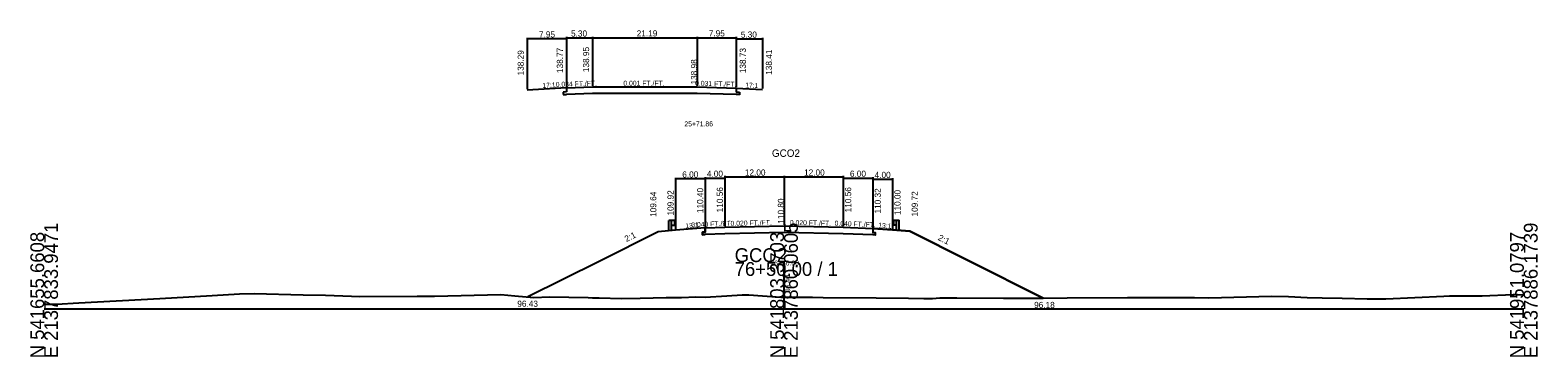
# Model space of a CAD drawing. Extents: x -14327 to 8886, y -10 to 39048.
# Drawn here: x 2997.2 to 3302.8, y 12990.3 to 13056.4 of the extents above; entities that cross this region are included whole.
import ezdxf

# ---------------------------------------------------------------- set-up
doc = ezdxf.new("R2010")
doc.units = 0
for name, color, linetype in [('Level 1', 7, 'Continuous'), ('Level 20', 7, 'Continuous'), ('Level 5', 7, 'Continuous'), ('Level 53', 7, 'Continuous'), ('Level 54', 7, 'Continuous'), ('Level 55', 7, 'Continuous'), ('Level 7', 7, 'Continuous'), ('RD_GPK_XS_Cell', 7, 'Continuous'), ('RD_XS_EwShp', 7, 'Continuous'), ('RD_XS_ExGround', 7, 'Continuous'), ('RD_XS_Pave', 7, 'Continuous'), ('RD_XS_TX_Baseline', 7, 'Continuous'), ('RD_XS_TX_Elev_EX', 7, 'Continuous'), ('RD_XS_TX_Elev_PR', 7, 'Continuous'), ('RD_XS_TX_Station', 7, 'Continuous')]:
    doc.layers.add(name, color=color, linetype=linetype)

msp = doc.modelspace()

# ---------------------------------------------------------------- linework, layer by layer
at = {"layer": 'Level 1'}
for p, q in [((3126.66, 13015.92), (3126.66, 13017.9)), ((3127.22, 13017.9), (3126.66, 13017.9)), ((3127.22, 13015.92), (3127.22, 13017.9)), ((3127.77, 13017.9), (3127.22, 13017.9)), ((3127.77, 13016.93), (3127.22, 13016.93)), ((3127.77, 13017.9), (3127.77, 13016.93)), ((3127.85, 13017.83), (3127.77, 13017.84)), ((3127.85, 13017), (3127.77, 13016.99)), ((3127.84, 13017.49), (3127.84, 13017.34)), ((3127.98, 13017.73), (3127.86, 13017.82)), ((3127.98, 13017.63), (3127.86, 13017.54)), ((3127.98, 13017.2), (3127.86, 13017.29)), ((3127.98, 13017.1), (3127.86, 13017.01)), ((3172.02, 13017.81), (3172.14, 13017.9)), ((3172.02, 13017.71), (3172.14, 13017.62)), ((3172.02, 13017.28), (3172.14, 13017.37)), ((3172.02, 13017.18), (3172.14, 13017.09)), ((3172.15, 13017.91), (3172.23, 13017.92)), ((3172.15, 13017.08), (3172.23, 13017.07)), ((3172.16, 13017.57), (3172.16, 13017.42)), ((3172.23, 13017.98), (3172.23, 13017.01)), ((3172.23, 13017.98), (3172.78, 13017.98)), ((3172.23, 13017.01), (3172.78, 13017.01)), ((3172.78, 13016), (3172.78, 13017.98)), ((3172.78, 13017.98), (3173.34, 13017.98)), ((3173.34, 13016), (3173.34, 13017.98))]:
    msp.add_line(p, q, dxfattribs=at)
for centre, radius, start, end in [((3127.91, 13017.49), 0.0651, 135, 180), ((3127.91, 13017.34), 0.0651, 180, 237.0105), ((3127.85, 13017.8), 0.026, 50.9495, 90), ((3127.85, 13017.03), 0.026, 270, 309.0504), ((3127.93, 13017.68), 0.0651, 309.0337, 50.9664), ((3127.93, 13017.15), 0.0651, 309.0337, 50.9664), ((3172.07, 13017.76), 0.0651, 129.0336, 230.9663), ((3172.07, 13017.23), 0.0651, 129.0336, 230.9663), ((3172.09, 13017.42), 0.0651, 302.9895, 0), ((3172.15, 13017.88), 0.026, 90, 129.0505), ((3172.09, 13017.57), 0.0651, 0, 45), ((3172.15, 13017.11), 0.026, 230.9496, 270)]:
    msp.add_arc(centre, radius, start, end, dxfattribs=at)
at = {"layer": 'Level 20'}
for p, q in [((3097.94, 13054.92), (3097.94, 13044.49)), ((3105.89, 13054.72), (3097.94, 13054.72)), ((3105.89, 13055.1), (3105.89, 13044.97)), ((3105.89, 13054.92), (3105.89, 13044.97)), ((3105.89, 13054.9), (3111.19, 13054.9)), ((3111.19, 13055.13), (3111.19, 13045.15)), ((3111.19, 13055.1), (3111.19, 13045.15)), ((3111.19, 13054.93), (3132.38, 13054.93)), ((3132.38, 13055.13), (3132.38, 13045.18)), ((3132.38, 13054.93), (3140.32, 13054.93)), ((3140.32, 13055.13), (3140.32, 13044.93)), ((3140.32, 13054.88), (3140.32, 13044.93)), ((3140.32, 13054.68), (3145.62, 13054.68)), ((3145.62, 13054.88), (3145.62, 13044.61)), ((3105.89, 13044.77), (3097.94, 13044.29)), ((3105.89, 13043.94), (3105.23, 13043.92)), ((3105.23, 13043.92), (3105.23, 13043.42)), ((3105.23, 13043.42), (3105.89, 13043.44)), ((3105.89, 13044.77), (3111.19, 13044.95)), ((3105.89, 13044.77), (3105.89, 13043.94)), ((3111.19, 13043.62), (3105.89, 13043.44)), ((3111.19, 13044.95), (3132.38, 13044.98)), ((3132.38, 13043.65), (3111.19, 13043.62)), ((3132.38, 13044.98), (3140.32, 13044.73)), ((3140.32, 13043.4), (3132.38, 13043.65)), ((3140.32, 13044.73), (3140.32, 13043.9)), ((3140.32, 13044.73), (3145.62, 13044.41)), ((3140.32, 13043.9), (3140.99, 13043.88)), ((3140.99, 13043.88), (3140.99, 13043.38)), ((3140.99, 13043.38), (3140.32, 13043.4))]:
    msp.add_line(p, q, dxfattribs=at)
at = {"layer": 'Level 5'}
for p, q in [((3134, 13016.4), (3134, 13015.56)), ((3168, 13016.32), (3168, 13015.48)), ((3134, 13015.56), (3133.5, 13015.54)), ((3133.5, 13015.54), (3133.5, 13015.04)), ((3133.5, 13015.04), (3134, 13015.06)), ((3138, 13015.22), (3134, 13015.06)), ((3150, 13015.46), (3138, 13015.22)), ((3162, 13015.22), (3150, 13015.46)), ((3168, 13014.98), (3162, 13015.22)), ((3168, 13015.48), (3168.5, 13015.46)), ((3168.5, 13014.96), (3168, 13014.98)), ((3168.5, 13015.46), (3168.5, 13014.96))]:
    msp.add_line(p, q, dxfattribs=at)
at = {"layer": 'Level 54'}
for p, q in [((3128, 13026.55), (3128, 13016.12)), ((3134, 13026.35), (3128, 13026.35)), ((3134, 13026.71), (3134, 13016.6)), ((3134, 13026.55), (3134, 13016.6)), ((3134, 13026.51), (3138, 13026.51)), ((3138, 13026.95), (3138, 13016.76)), ((3138, 13026.75), (3150, 13026.75)), ((3138, 13026.71), (3138, 13016.76)), ((3150, 13026.95), (3150, 13017)), ((3150, 13026.75), (3162, 13026.75)), ((3162, 13026.95), (3162, 13016.76)), ((3162, 13026.71), (3162, 13016.76)), ((3162, 13026.51), (3168, 13026.51)), ((3168, 13026.71), (3168, 13016.52)), ((3168, 13026.47), (3168, 13016.52)), ((3168, 13026.27), (3172, 13026.27)), ((3172, 13026.47), (3172, 13016.2))]:
    msp.add_line(p, q, dxfattribs=at)
at = {"layer": 'Level 7'}
for p, q in [((3134, 13016.4), (3128, 13015.92)), ((3168, 13016.32), (3172, 13016)), ((3172, 13016), (3175.5, 13015.72)), ((3124.5, 13015.64), (3112.5, 13009.64)), ((3128, 13015.92), (3124.5, 13015.64)), ((3175.5, 13015.72), (3187.5, 13009.72)), ((3112.5, 13009.64), (3098.09, 13002.43)), ((3187.5, 13009.72), (3202.57, 13002.18))]:
    msp.add_line(p, q, dxfattribs=at)
at = {"layer": 'RD_GPK_XS_Cell'}
for p, q in [((3150, 13000), (3150, 13009.49)), ((3000, 13000), (3150, 13000)), ((3150, 13000), (3300, 13000))]:
    msp.add_line(p, q, dxfattribs=at)
at = {"layer": 'RD_XS_EwShp'}
msp.add_lwpolyline([(3194.52, 13002.16), (3198.96, 13002.15), (3202.57, 13002.18), (3187.5, 13009.72), (3175.5, 13015.72), (3172, 13016), (3168, 13016.32), (3168, 13015.48), (3168.5, 13015.46), (3168.5, 13014.96), (3168, 13014.98), (3162, 13015.22), (3150, 13015.46), (3138, 13015.22), (3134, 13015.06), (3133.5, 13015.04), (3133.5, 13015.54), (3134, 13015.56), (3134, 13016.4), (3128, 13015.92), (3124.5, 13015.64), (3112.5, 13009.64), (3098.09, 13002.43), (3099.29, 13002.32), (3102.48, 13002.42), (3110.32, 13002.32), (3111.19, 13002.27), (3112.5, 13002.27), (3117.05, 13002.14), (3120.82, 13002.21), (3126.14, 13002.29), (3129.21, 13002.31), (3132.15, 13002.44), (3134.03, 13002.39), (3138.41, 13002.66), (3141.5, 13002.85), (3142.88, 13002.85), (3149.35, 13002.41), (3150, 13002.4), (3155.79, 13002.36), (3157.97, 13002.33), (3168.7, 13002.25), (3175.26, 13002.16), (3178.34, 13002.09), (3180.08, 13002.14), (3181.61, 13002.25), (3185.02, 13002.26)], close=True, dxfattribs=at)
at = {"layer": 'RD_XS_ExGround'}
for p, q in [((3000, 13000.99), (3001.17, 13000.94)), ((3001.17, 13000.94), (3002.49, 13000.99)), ((3002.49, 13000.99), (3007.01, 13001.25)), ((3007.01, 13001.25), (3023.45, 13002.13)), ((3023.45, 13002.13), (3034.08, 13002.72)), ((3034.08, 13002.72), (3039.58, 13003.05)), ((3039.58, 13003.05), (3042.6, 13003.16)), ((3042.6, 13003.16), (3052.5, 13002.87)), ((3052.5, 13002.87), (3057.07, 13002.82)), ((3057.07, 13002.82), (3062.31, 13002.59)), ((3062.31, 13002.59), (3063.97, 13002.49)), ((3063.97, 13002.49), (3075.61, 13002.59)), ((3075.61, 13002.59), (3078.32, 13002.61)), ((3078.32, 13002.61), (3079.12, 13002.61)), ((3079.12, 13002.61), (3092.62, 13002.9)), ((3092.62, 13002.9), (3095.45, 13002.68)), ((3095.45, 13002.68), (3099.29, 13002.32)), ((3099.29, 13002.32), (3102.48, 13002.42)), ((3102.48, 13002.42), (3110.32, 13002.32)), ((3110.32, 13002.32), (3111.19, 13002.27)), ((3111.19, 13002.27), (3112.5, 13002.27)), ((3112.5, 13002.27), (3117.05, 13002.14)), ((3117.05, 13002.14), (3120.82, 13002.21)), ((3120.82, 13002.21), (3126.14, 13002.29)), ((3126.14, 13002.29), (3129.21, 13002.31)), ((3129.21, 13002.31), (3132.15, 13002.44)), ((3132.15, 13002.44), (3134.03, 13002.39)), ((3134.03, 13002.39), (3138.41, 13002.66)), ((3138.41, 13002.66), (3141.5, 13002.85)), ((3141.5, 13002.85), (3142.88, 13002.85)), ((3142.88, 13002.85), (3149.35, 13002.41)), ((3149.35, 13002.41), (3150, 13002.4)), ((3150, 13002.4), (3155.79, 13002.36)), ((3155.79, 13002.36), (3157.97, 13002.33)), ((3157.97, 13002.33), (3168.7, 13002.25)), ((3168.7, 13002.25), (3175.26, 13002.16)), ((3175.26, 13002.16), (3178.34, 13002.09)), ((3178.34, 13002.09), (3180.08, 13002.14)), ((3180.08, 13002.14), (3181.61, 13002.25)), ((3181.61, 13002.25), (3185.02, 13002.26)), ((3185.02, 13002.26), (3194.52, 13002.16)), ((3194.52, 13002.16), (3198.96, 13002.15)), ((3198.96, 13002.15), (3207.43, 13002.23)), ((3207.43, 13002.23), (3219.62, 13002.33)), ((3219.62, 13002.33), (3220.84, 13002.34)), ((3220.84, 13002.34), (3221.41, 13002.35)), ((3221.41, 13002.35), (3233.26, 13002.29)), ((3233.26, 13002.29), (3236.16, 13002.26)), ((3236.16, 13002.26), (3248.86, 13002.59)), ((3248.86, 13002.59), (3252.26, 13002.51)), ((3252.26, 13002.51), (3256.05, 13002.34)), ((3256.05, 13002.34), (3259.08, 13002.26)), ((3259.08, 13002.26), (3263.14, 13002.15)), ((3263.14, 13002.15), (3268.21, 13002.02)), ((3268.21, 13002.02), (3271.99, 13002.04)), ((3271.99, 13002.04), (3283.81, 13002.58)), ((3283.81, 13002.58), (3284.9, 13002.64)), ((3284.9, 13002.64), (3291.55, 13002.63)), ((3291.55, 13002.63), (3297.81, 13002.91)), ((3297.81, 13002.91), (3298.73, 13002.94)), ((3298.73, 13002.94), (3300, 13002.88))]:
    msp.add_line(p, q, dxfattribs=at)
at = {"layer": 'RD_XS_Pave'}
for p, q in [((3134, 13016.4), (3138, 13016.56)), ((3138, 13016.56), (3150, 13016.8)), ((3150, 13016.8), (3162, 13016.56)), ((3162, 13016.56), (3168, 13016.32))]:
    msp.add_line(p, q, dxfattribs=at)

# ---------------------------------------------------------------- texts
at = {"layer": 'Level 20'}
for s, height, p in [('7.95', 1.25, (3100.32, 13054.97)), ('5.30', 1.25, (3106.82, 13055.15)), ('21.19', 1.25, (3120.14, 13055.18)), ('7.95', 1.25, (3134.75, 13055.18)), ('5.30', 1.25, (3141.25, 13054.93)), ('25+71.86', 1, (3129.8, 13036.98))]:
    msp.add_text(s, height=height, dxfattribs=at).set_placement(p)
for s, height, rotation, p in [('138.77', 1.25, 90, (3105.19, 13047.77)), ('138.95', 1.25, 90, (3110.49, 13047.95)), ('138.73', 1.25, 90, (3142.27, 13047.73)), ('138.29', 1.25, 90, (3097.24, 13047.29)), (' 138.98', 1.25, 90, (3132.38, 13044.98)), ('138.41', 1.25, 90, (3147.57, 13047.41)), ('17:1', 1, 3.4568, (3101.03, 13044.73)), ('0.034 FT./FT.', 1, 1.9283, (3103.73, 13044.95)), ('0.001 FT./FT.', 1, 0.0833, (3117.43, 13045.21)), ('0.031 FT./FT.', 1, 358.1997, (3131.97, 13045.24)), ('17:1', 1, 356.5432, (3142.11, 13044.87))]:
    msp.add_text(s, height=height, rotation=rotation, dxfattribs=at).set_placement(p)
at = {"layer": 'Level 53'}
for s, rotation, p in [('109.64', 90, (3124.12, 13018.64)), ('109.92', 90, (3127.62, 13018.92)), ('110.40', 90, (3133.62, 13019.4)), ('110.56', 90, (3137.62, 13019.56)), ('110.56', 90, (3163.62, 13019.56)), ('110.32', 90, (3169.63, 13019.32)), ('110.00', 90, (3173.63, 13019)), ('109.72', 90, (3177.13, 13018.72)), ('2:1', 26.5651, (3118.05, 13013.53)), ('2:1', 333.4349, (3181.11, 13014.03))]:
    msp.add_text(s, height=1.25, rotation=rotation, dxfattribs=at).set_placement(p)
for s, p in [('96.43', (3095.93, 13000.43)), ('96.18', (3200.71, 13000.18))]:
    msp.add_text(s, height=1.25, dxfattribs=at).set_placement(p)
at = {"layer": 'Level 54'}
for s, p in [('12.00', (3142.07, 13027)), ('12.00', (3154.07, 13027)), ('6.00', (3129.37, 13026.6)), ('4.00', (3134.37, 13026.76)), ('6.00', (3163.37, 13026.76)), ('4.00', (3168.37, 13026.52))]:
    msp.add_text(s, height=1.25, dxfattribs=at).set_placement(p)
at = {"layer": 'Level 55'}
for s, rotation, p in [('13:1', 4.5739, (3130.03, 13016.33)), ('0.040 FT./FT.', 2.2906, (3131.22, 13016.54)), ('0.020 FT./FT.', 1.1458, (3139.17, 13016.83)), ('0.020 FT./FT.', 358.8542, (3151.18, 13017.02)), ('0.040 FT./FT.', 357.7094, (3160.24, 13016.88)), ('13:1', 355.4261, (3169.07, 13016.48))]:
    msp.add_text(s, height=1, rotation=rotation, dxfattribs=at).set_placement(p)
at = {"layer": 'RD_GPK_XS_Cell'}
for s, p in [('E 2137833.9471', (3002.8, 12990)), ('E 2137860.0605', (3152.8, 12990)), ('E 2137886.1739', (3302.8, 12990)), ('N 541655.6608', (3000, 12990)), ('N 541803.3703', (3150, 12990)), ('N 541951.0797', (3300, 12990))]:
    msp.add_text(s, height=2.8, rotation=90, dxfattribs=at).set_placement(p)
for s, p in [('GCO2', (3140, 13009.49)), ('76+50.00 / 1', (3140, 13006.69))]:
    msp.add_text(s, height=2.8, dxfattribs=at).set_placement(p)
at = {"layer": 'RD_XS_TX_Baseline'}
msp.add_text('GCO2', height=1.5, dxfattribs=at).set_placement((3147.55, 13030.8))
at = {"layer": 'RD_XS_TX_Elev_EX'}
msp.add_text('96.40', height=1, rotation=90, dxfattribs=at).set_placement((3151.25, 13003.4))
at = {"layer": 'RD_XS_TX_Elev_PR'}
msp.add_text(' 110.80', height=1.25, rotation=90, dxfattribs=at).set_placement((3150, 13016.8))
at = {"layer": 'RD_XS_TX_Station'}
msp.add_text('76+50.00', height=1, dxfattribs=at).set_placement((3147.23, 13008.8))

doc.saveas('drawing.dxf')
